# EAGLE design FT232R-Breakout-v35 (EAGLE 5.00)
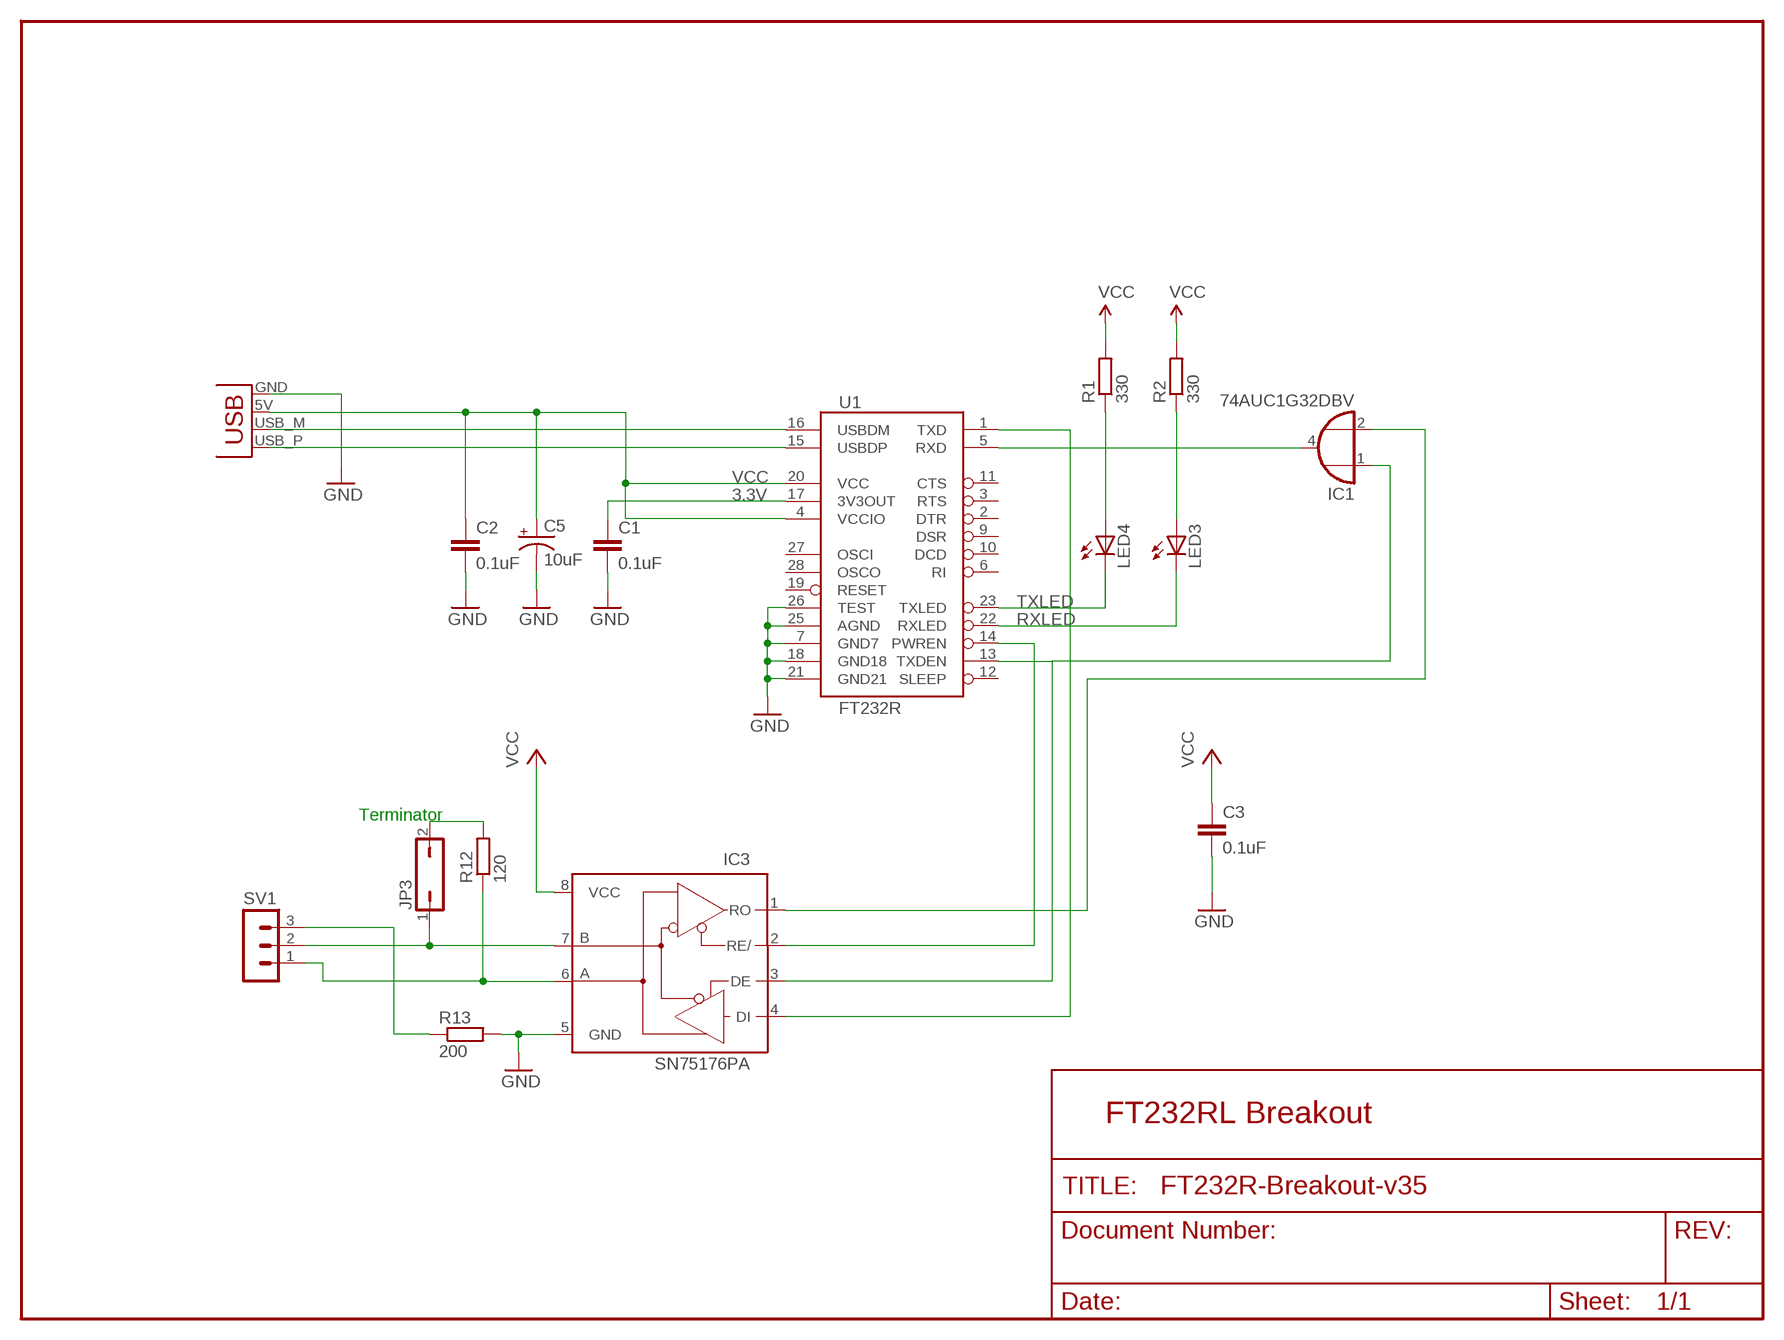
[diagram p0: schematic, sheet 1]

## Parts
C1  0.1uF  CAP0805  [0805]
C2  0.1uF  CAP0603  [0603]
C3  0.1uF  CAP0805  [0805]
C5  10uF  CAP_POLPTH2  [CPOL-RADIAL-10UF-25V]
IC1  74AUC1G32DBV  [SOT23-5]
IC3  SN75176PA  [DIL08]
JP3  JP1Q  [JP1]
LED3  LEDCHIP-LED0805  [CHIP-LED0805]
LED4  LEDCHIP-LED0805  [CHIP-LED0805]
R1  330  R-EU_M0805  [M0805]
R2  330  R-EU_M0805  [M0805]
R12  120  R-EU_0207/10  [0207/10]
R13  200  R-EU_0207/10  [0207/10]
SV1  MA03-1  [MA03-1]
U1  FT232R  FT232RLSSOP  [SSOP28DB]
X1  USBPCB  [USB-A-PCB]

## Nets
3.3V [power]: C1.1 U1.17(3V3OUT)
GND [power]: C1.2 C2.2 C3.2 C5.2(-) IC3.5(GND) R13.2 U1.7(GND7) U1.18(GND18) U1.21(GND21) U1.25(AGND) U1.26(TEST) X1.GND
N$1: LED4.A R1.1
N$2: LED3.A R2.1
N$3: IC3.7(B) JP3.1 SV1.2
N$4: IC1.4(O) U1.5(RXD)
N$5: IC1.1(I0) IC3.3(DE) U1.13(TXDEN)
N$7: IC1.2(I1) IC3.1(RO)
N$8: IC3.2(RE/) U1.14(PWREN)
N$9: IC3.4(DI) U1.1(TXD)
N$10: R13.1 SV1.3
N$11: JP3.2 R12.2
N$28: IC3.6(A) R12.1 SV1.1
RXLED: LED3.C U1.22(RXLED)
TXLED: LED4.C U1.23(TXLED)
USB_D+: U1.15(USBDP) X1.USB_P(D+)
USB_D-: U1.16(USBDM) X1.USB_M(D-)
VCC [power]: C2.1 C3.1 C5.1(+) IC3.8(VCC) R1.2 R2.2 U1.4(VCCIO) U1.20(VCC) X1.5V(VBUS)
Unconnected: U1.2(DTR) U1.3(RTS) U1.6(RI) U1.9(DSR) U1.10(DCD) U1.11(CTS) U1.12(SLEEP) U1.19(RESET) U1.27(OSCI) U1.28(OSCO)

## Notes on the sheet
- Terminator
- FT232RL Breakout

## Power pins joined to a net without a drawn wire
GND: IC1.3(GND)
VCC: IC1.5(VCC)

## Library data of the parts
C1-C3 = SparkFun:CAP: Capacitor
C5 = SparkFun:CAP_POL: Capacitor Polarized
IC1 = 74xx-little-de:74*1G32: 2-input OR gate
IC3 = Evert:SN75176: +5V, Fail-Safe, 40Mbps, Profibus RS-485/RS-422 Transceivers
JP3 = jumper:JP1Q: JUMPER
LED3 LED4 = led:LED: LED
R1 R2 R12 R13 = rcl:R-EU_: RESISTOR, European symbol
SV1 = con-lstb:MA03-1: PIN HEADER
U1 = SparkFun:FT232RL: USB UART FT232RL 4th Generation USB UART (USB <-> Serial) Controller. Spark Fun Electronics SKU : COM-00650
X1 = SparkFun:USB: USB Connectors USB-B-PTH is fully proven SKU : PRT-00139 USB-miniB is fully proven SKU : PRT-00587 USB-A-PCB is untested. USB-A-H is throughly reviewed, but untested. Spark Fun Electronics SKU : PRT-00437 USB-B-SMT is throughly reviewed, but untested. Needs silkscreen touching up. USB-A-S has not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

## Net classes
0 default: width 0.254 mm
1 power: width 0.254 mm

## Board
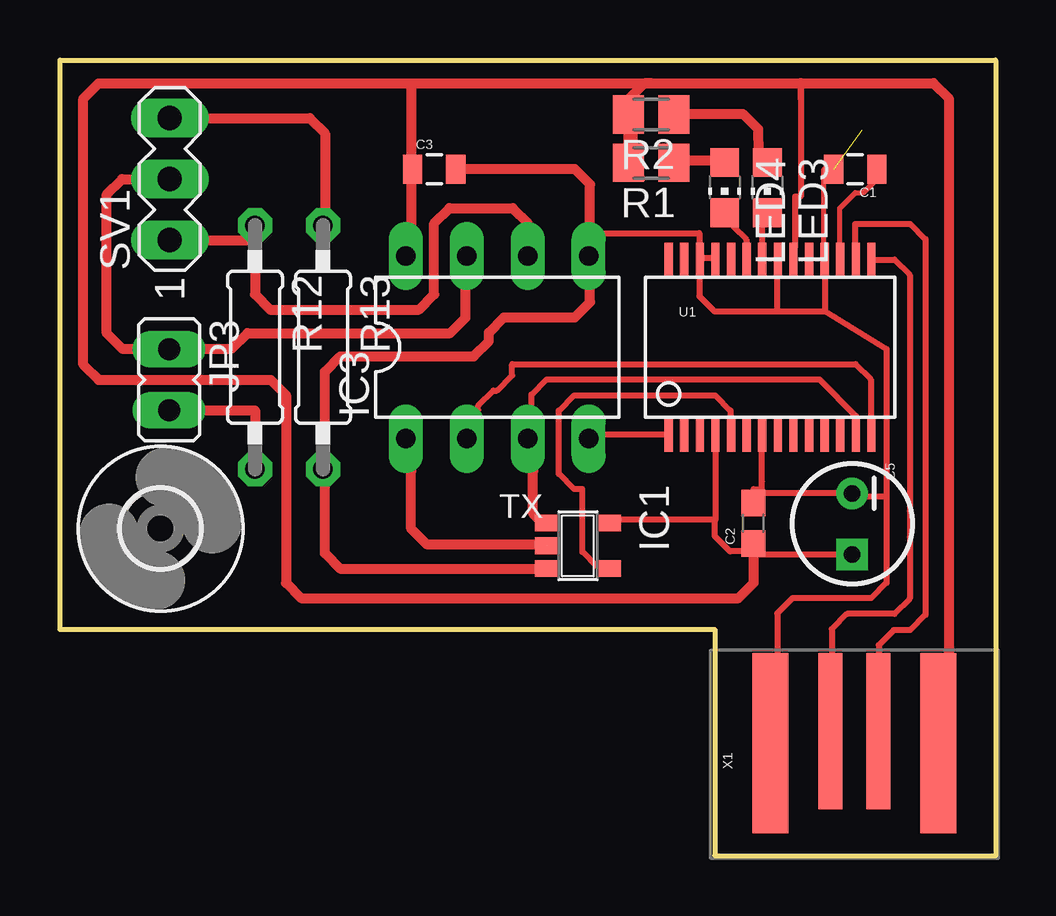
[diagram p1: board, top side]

Size 39 x 33.15 mm. Coordinates in mm from the lower left corner, seen from the top.
Outline: 0,33.15 39,33.15 39,0 27.3,0 27.3,9.43 0,9.43 0,33.15
Copper layers (1*16): Top 0.035mm / dielectric 1.5mm / Bottom 0.035mm
Design rules "SparkFun": minimum track width 8mil, minimum drill 20mil, track to track 8mil, track to pad 8mil, pad to pad 8mil, via to via 8mil, smd to smd 8mil, copper to edge 10mil, drill to drill 8mil, minimum pad ring 12mil, minimum via ring 10mil, stop-mask expansion 4mil, vias tented up to drill 20mil, thermal gap 10mil

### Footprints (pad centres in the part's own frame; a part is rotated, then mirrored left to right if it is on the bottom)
0805 = smd 0.8 x 1.2: 1 -0.9,0; 2 0.9,0
0603 = smd 1.1 x 1: 1 -0.85,0; 2 0.85,0
CPOL-RADIAL-10UF-25V = drill 0.7 square: 1 1.27,0 | drill 0.7 round: 2 -1.27,0
SOT23-5 = smd 0.69 x 0.99: 1 -0.95,-1.29; 2 0,-1.29; 3 0.95,-1.29; 4 0.95,1.3; 5 -0.95,1.3
DIL08 = drill 0.813 long: 1 -3.81,-3.81; 2 -1.27,-3.81; 3 1.27,-3.81; 4 3.81,-3.81; 5 3.81,3.81; 6 1.27,3.81; 7 -1.27,3.81; 8 -3.81,3.81
JP1 = drill 0.914 long: 1 0,-1.27; 2 0,1.27
CHIP-LED0805 = smd 1.2 x 1.2: A 0,-1.05; C 0,1.05
M0805 = smd 1.3 x 1.6: 1 -0.95,0; 2 0.95,0
0207/10 = drill 0.813 octagon: 1 -5.08,0; 2 5.08,0
MA03-1 = drill 1.016 long: 1 -2.54,0; 2 0,0; 3 2.54,0
SSOP28DB = smd 0.348 x 1.397: 1 -4.225,-3.656; 2 -3.575,-3.656; 3 -2.925,-3.656; 4 -2.275,-3.656; 5 -1.625,-3.656; 6 -0.975,-3.656; 7 -0.325,-3.656; 8 0.325,-3.656; 9 0.975,-3.656; 10 1.625,-3.656; 11 2.275,-3.656; 12 2.925,-3.656; 13 3.575,-3.656; 14 4.225,-3.656; 15 4.225,3.656; 16 3.575,3.656; 17 2.925,3.656; 18 2.275,3.656; 19 1.625,3.656; 20 0.975,3.656; 21 0.325,3.656; 22 -0.325,3.656; 23 -0.975,3.656; 24 -1.625,3.656; 25 -2.275,3.656; 26 -2.925,3.656; 27 -3.575,3.656; 28 -4.225,3.656
3,2 = hole 3.2: 0,0
USB-A-PCB = smd 7.5 x 1.5: 5V -0.2,-3.5; GND -0.2,3.5 | smd 6.5 x 1: USB_M 0.3,-1; USB_P 0.3,1

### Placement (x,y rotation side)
C1  33.15,28.6 180 top
C2  28.91,13.85 90 top
C3  15.6,28.6 0 top
C5  33.02,13.82 270 top
IC1  21.6,12.91 270 top
IC3  18.23,21.18 0 top
JP3  4.55,19.83 180 top
LED3  29.48,27.83 180 top
LED4  27.71,27.83 180 top
R1  24.65,28.87 180 top
R2  24.65,30.88 180 top
R12  8.13,21.18 270 top
R13  10.96,21.18 270 top
SV1  4.57,28.19 90 top
U1  29.6,21.18 0 top
U$1  [3,2]  4.2,13.62 0 top
X1  33.12,4.88 90 top

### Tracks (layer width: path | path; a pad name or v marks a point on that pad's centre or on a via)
3.3V
  Top 0.203: U1.17 32.5,24.86 32.5,26.98 32.52,26.98 33.15,27.61 33.15,27.62 33.49,27.62 34.12,28.26 34.12,28.53 C1.1
GND  (1 unrouted)
  Top 0.203: C1.2 31.85,28.6 31.85,24.86 U1.18
  Top 0.254: IC1.3 19.98,11.89 | 31.91,22.67 31.91,24.16 U1.18 | 27.34,24.16 U1.25 27.34,24.92 26.83,24.92 U1.26 26.65,24.84 | 31.91,22.67 34.45,21.11 34.45,16.03 34.45,14.95 | IC3.5 22.52,25.94 26.65,25.94 26.65,24.84 | U1.7 29.25,17.52 29.25,15.6 | 29.9,22.67 31.91,22.67 | 26.65,24.84 26.65,23.31 27.29,22.67 29.9,22.67 | U1.21 29.9,24.84 29.9,22.67 | 34.45,14.95 32.83,14.95 32.83,15.09 C5.2 28.93,15.09 | 28.93,15.09 C2.2 | 28.93,15.09 28.93,15.28 29.25,15.28 29.25,15.6 | 29.25,15.6 29.25,15.59 | X1.GND 29.9,5.65 29.9,10.09 30.54,10.73 33.82,10.73 34.45,11.36 34.45,14.95
  Top 0.406: 11.05,16.19 11.05,16.1 R13.2 11.05,16.19 | 22.1,24.99 22.1,25.02 | 22.1,25.02 22.1,25.35 | 22.1,24.99 IC3.5 22.07,24.99 22.1,25.02 | 22.1,24.99 22.1,23.06 21.46,22.43 18.51,22.43 17.88,21.79 17.88,21.44 17.24,20.8 11.69,20.8 11.05,20.16 11.05,16.19 | IC1.3 11.69,11.96 11.05,12.6 11.05,16.19 | C3.2 21.46,28.6 22.1,27.96 22.1,25.02
N$1
  Top 0.254: 27.34,28.98 LED4.A | R1.1 26.07,28.98
  Top 0.406: 26.07,28.98 27.34,28.98
N$2
  Top 0.254: 29.12,29.24 LED3.A | R2.1 25.75,30.9
  Top 0.406: 25.75,30.9 28.46,30.9 29.09,30.29 29.12,29.24
N$3
  Top 0.406: SV1.2 2.59,28.19 1.95,27.55 1.95,21.76 2.59,21.12 4.55,21.12 | 4.55,21.12 4.55,21.23 | 4.55,21.12 JP3.1 4.22,21.23 | IC3.7 16.9,24.99 16.9,22.41 16.27,21.77 7.81,21.77 7.16,21.12 4.22,21.12 4.22,21.23 | 4.22,21.23 4.22,21.45
N$4
  Top 0.254: U1.5 27.95,17.52 27.95,18.54 27.32,19.18 21.44,19.18 20.8,18.54 20.8,15.91 21.44,15.28 21.78,15.28 21.78,12.66 22.41,12.03 23.08,12.03 23.08,11.96 IC1.4
N$5
  Top 0.254: U1.13 33.18,18.06 33.18,18.32 31.66,19.84 20.29,19.84 19.65,19.2 19.65,18.57 IC3.3
  Top 0.406: IC1.1 19.98,14 19.72,14.25 19.72,16.03 IC3.3
N$7
  Top 0.254: 19.98,12.98 IC1.2
  Top 0.406: 19.98,12.98 15.28,12.98 14.64,13.62 14.64,16.03 IC3.1
N$8
  Top 0.254: IC3.2 17.44,18.57 17.44,18.74 18.07,19.37 18.21,19.37 18.85,20.01 18.85,20.48 33.16,20.48 33.8,19.84 33.8,17.52 U1.14
N$9
  Top 0.254: U1.1 25.31,17.55 22.52,17.55 IC3.4
N$10
  Top 0.406: R13.1 11.05,26.26 11.05,30.1 10.41,30.73 SV1.3
N$11
  Top 0.406: R12.2 8.12,15.93 | R12.2 | JP3.2 8.12,18.55 R12.2
N$28
  Top 0.406: R12.1 8.12,26.32 | SV1.1 8.12,25.65 R12.1 | R12.1 | R12.1 8.12,23.39 8.76,22.75 14.96,22.75 15.6,23.39 15.6,26.34 16.24,26.98 18.87,26.98 19.5,26.34 IC3.6
RXLED
  Top 0.254: LED3.C 29.25,26.78 29.25,24.84 U1.22
TXLED
  Top 0.254: LED4.C 28.1,26.19 28.61,25.68 28.61,25.43 U1.23
USB_D+
  Top 0.254: U1.15 34.79,24.84 35.43,24.2 35.43,10.71 34.79,10.08 32.81,10.08 32.18,9.44 32.18,5.18 X1.USB_P
USB_D-
  Top 0.254: U1.16 33.15,24.84 33.15,26.32 35.44,26.32 36.08,25.69 36.08,10.04 35.44,9.4 34.76,9.4 34.12,8.77 34.12,8.12 X1.USB_M
VCC
  Top 0.254: U1.20 30.64,25.43 30.64,27.46 30.88,27.46 30.88,31.53 | 24.29,28.22 R1.2 23.79,29.49 | 23.79,30.25 R2.2 23.28,30.25 | 27.3,14 23.28,14 IC1.5 | 27.3,14 27.34,14 27.34,17.05 U1.4 | 30.88,32.17 30.88,31.53 | 37.05,4.68 X1.5V | 30.88,31.53 30.88,32.19 | C5.1 28.93,12.55 28.93,12.68 27.94,12.68 27.3,13.31 27.3,14
  Top 0.406: 23.73,30.88 23.73,31.54 24.36,32.17 24.7,32.17 | 24.7,32.17 30.88,32.17 | 30.88,32.19 36.41,32.19 37.05,31.55 37.05,4.68 | C2.1 28.93,12.55 28.93,11.36 28.29,10.73 10.06,10.73 9.42,11.36 9.42,19.19 8.79,19.83 1.61,19.83 0.98,20.46 0.98,31.54 1.61,32.17 13.65,32.17 | 14.62,28.6 C3.1 | IC3.8 14.62,25.2 14.62,28.6 | 13.65,32.17 13.67,32.17 | 13.65,32.17 14.62,32.17 | 14.62,32.17 24.7,32.17 | 14.62,32.17 14.62,28.6
  Top 0.61: 23.79,30.25 23.79,29.49 | 23.73,30.88 R2.2

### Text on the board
tPlace: TX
